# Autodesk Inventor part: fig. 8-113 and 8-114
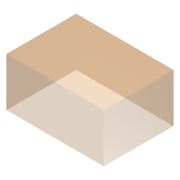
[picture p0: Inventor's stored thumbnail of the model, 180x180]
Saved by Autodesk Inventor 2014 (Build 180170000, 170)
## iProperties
Created: 2013-07
Part Number: fig. 8-113 and 8-114
Material: Generic
Document SubType Name: Modeling
Designer: CADCIM
Density: 1 g/cm^3
Appearance: Default
Author: CADCIM
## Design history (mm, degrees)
sketch "Sketch1"
  geometry: L1 (-10, 7.167)-(10, 7.167); L2 (10, 7.167)-(10, -7.167); L3 (10, -7.167)-(-10, -7.167); L4 (-10, -7.167)-(-10, 7.167); L5 (-10, 7.167)-(10, -7.167); L6 (10, 7.167)-(-10, -7.167); 1 further point
  constraints: 12 end point, 2 midpoint, 2 parallel, 1 horizontal, 1 perpendicular
  dimensions: "d0" = 20 distance of L2.end L3.end
extrude_surface "ExtrusionSrf1" sketch "Sketch1" dims "d1" = 10, "d2" = 0
patch "Boundary Patch1" dims "d3" = 5, "d4" = 0
body "Srf1"
body "Srf2"
